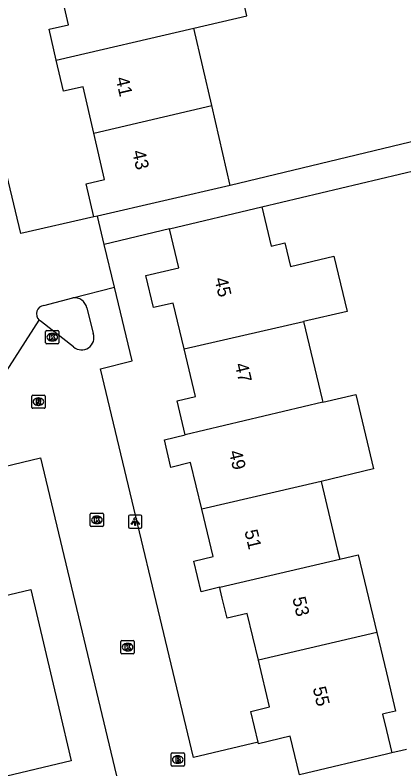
# Model space of a CAD drawing. Extents: x 158474 to 159560, y 388525 to 389605.
# Drawn here: x 159472 to 159501.3, y 388683.1 to 388739.9 of the extents above; entities that cross this region are included whole.
import ezdxf

# ---------------------------------------------------------------- set-up
doc = ezdxf.new("R2010")
doc.units = 0
for name, color, linetype in [('IMGEO_Brandkraan', 7, 'Continuous'), ('IMGEO_Kolk', 7, 'Continuous'), ('IMGEO_Lichtpunt', 7, 'Continuous'), ('IMGEO_Pand', 7, 'Continuous'), ('IMGEO_Pand_nummerreeks', 7, 'Continuous'), ('IMGEO_Rijbaan_lokaal_open', 7, 'Continuous'), ('IMGEO_Rioolput', 7, 'Continuous'), ('IMGEO_Voetpad_open', 7, 'Continuous')]:
    doc.layers.add(name, color=color, linetype=linetype)

msp = doc.modelspace()

# ---------------------------------------------------------------- linework, layer by layer
at = {"layer": 'IMGEO_Brandkraan'}
for p, q in [((159483.777, 388683.342), (159483.777, 388684.194)), ((159483.852, 388684.268), (159484.704, 388684.268)), ((159484.265, 388684.048), (159484.29, 388684.048)), ((159484.778, 388684.194), (159484.778, 388683.342)), ((159484.288, 388683.488), (159484.263, 388683.488)), ((159484.704, 388683.268), (159483.852, 388683.268))]:
    msp.add_line(p, q, dxfattribs=at)
for points in [[(159483.777, 388683.342), (159483.777, 388684.194)], [(159483.852, 388684.268), (159484.704, 388684.268)], [(159484.778, 388684.194), (159484.778, 388683.342)], [(159484.125, 388683.968), (159484.125, 388683.568), (159484.338, 388683.568)], [(159484.356, 388683.968), (159484.125, 388683.968)], [(159484.304, 388683.887), (159484.25, 388683.887), (159484.25, 388683.811)], [(159484.25, 388683.811), (159484.303, 388683.811)], [(159484.312, 388683.735), (159484.25, 388683.735), (159484.25, 388683.654)], [(159484.25, 388683.654), (159484.312, 388683.654)], [(159484.704, 388683.268), (159483.852, 388683.268)]]:
    msp.add_lwpolyline(points, dxfattribs=at)
for centre, radius, start, end in [((159483.854, 388684.192), 0.0765, 91.552, 178.448), ((159483.854, 388684.192), 0.0765, 91.552, 178.448), ((159484.702, 388684.192), 0.0765, 1.552, 88.448), ((159484.702, 388684.192), 0.0765, 1.552, 88.448), ((159484.305, 388683.849), 0.0379, 267.8285, 90.9355), ((159484.313, 388683.694), 0.0404, 269.8759, 90.5077), ((159484.344, 388683.819), 0.251, 268.6676, 293.5347), ((159484.36, 388683.823), 0.145, 59.4692, 91.5367), ((159484.385, 388683.87), 0.0922, 285.5137, 58.1501), ((159484.39, 388683.678), 0.105, 301.3115, 78.989), ((159483.854, 388683.344), 0.0765, 181.552, 268.448), ((159483.854, 388683.344), 0.0765, 181.552, 268.448), ((159484.702, 388683.344), 0.0765, 271.552, 358.448), ((159484.702, 388683.344), 0.0765, 271.552, 358.448)]:
    msp.add_arc(centre, radius, start, end, dxfattribs=at)
for centre, major_axis, ratio, start_param, end_param in [((159484.264, 388683.768), (-0.387, 0.002), 0.722429, 4.712389, 7.853982), ((159484.289, 388683.768), (-0.39, 0.002), 0.717154, 1.570796, 4.712389)]:
    msp.add_ellipse(centre, major_axis=major_axis, ratio=ratio, start_param=start_param, end_param=end_param, dxfattribs=at)
at = {"layer": 'IMGEO_Kolk'}
for p, q in [((159474.326, 388715.187), (159474.326, 388716.039)), ((159474.401, 388716.113), (159475.253, 388716.113)), ((159474.814, 388715.893), (159474.839, 388715.893)), ((159475.327, 388716.039), (159475.327, 388715.187)), ((159474.837, 388715.333), (159474.812, 388715.333)), ((159475.253, 388715.113), (159474.401, 388715.113)), ((159477.69, 388701.413), (159477.69, 388702.265)), ((159477.765, 388702.339), (159478.617, 388702.339)), ((159478.691, 388702.265), (159478.691, 388701.413)), ((159478.178, 388702.119), (159478.203, 388702.119)), ((159478.617, 388701.339), (159477.765, 388701.339)), ((159478.201, 388701.559), (159478.176, 388701.559)), ((159480, 388691.82), (159480, 388692.672)), ((159480.075, 388692.746), (159480.927, 388692.746)), ((159481.001, 388692.672), (159481.001, 388691.82)), ((159480.488, 388692.526), (159480.513, 388692.526)), ((159480.927, 388691.746), (159480.075, 388691.746)), ((159480.511, 388691.966), (159480.486, 388691.966))]:
    msp.add_line(p, q, dxfattribs=at)
for points in [[(159474.326, 388715.187), (159474.326, 388716.039)], [(159474.401, 388716.113), (159475.253, 388716.113)], [(159475.327, 388716.039), (159475.327, 388715.187)], [(159474.647, 388715.813), (159474.77, 388715.813), (159474.77, 388715.662), (159474.9, 388715.813), (159475.064, 388715.813), (159474.918, 388715.662), (159475.071, 388715.413), (159474.919, 388715.413), (159474.834, 388715.577), (159474.77, 388715.51), (159474.77, 388715.413), (159474.647, 388715.413), (159474.647, 388715.813)], [(159475.253, 388715.113), (159474.401, 388715.113)], [(159477.69, 388701.413), (159477.69, 388702.265)], [(159477.765, 388702.339), (159478.617, 388702.339)], [(159478.691, 388702.265), (159478.691, 388701.413)], [(159478.011, 388702.039), (159478.134, 388702.039), (159478.134, 388701.888), (159478.264, 388702.039), (159478.428, 388702.039), (159478.282, 388701.888), (159478.435, 388701.639), (159478.283, 388701.639), (159478.198, 388701.803), (159478.134, 388701.736), (159478.134, 388701.639), (159478.011, 388701.639), (159478.011, 388702.039)], [(159478.617, 388701.339), (159477.765, 388701.339)], [(159480, 388691.82), (159480, 388692.672)], [(159480.075, 388692.746), (159480.927, 388692.746)], [(159481.001, 388692.672), (159481.001, 388691.82)], [(159480.321, 388692.446), (159480.444, 388692.446), (159480.444, 388692.295), (159480.574, 388692.446), (159480.738, 388692.446), (159480.592, 388692.295), (159480.745, 388692.046), (159480.593, 388692.046), (159480.508, 388692.21), (159480.444, 388692.143), (159480.444, 388692.046), (159480.321, 388692.046), (159480.321, 388692.446)], [(159480.927, 388691.746), (159480.075, 388691.746)]]:
    msp.add_lwpolyline(points, dxfattribs=at)
for centre, start, end in [((159474.403, 388716.037), 91.552, 178.448), ((159474.403, 388716.037), 91.552, 178.448), ((159475.251, 388716.037), 1.552, 88.448), ((159475.251, 388716.037), 1.552, 88.448), ((159474.403, 388715.189), 181.552, 268.448), ((159474.403, 388715.189), 181.552, 268.448), ((159475.251, 388715.189), 271.552, 358.448), ((159475.251, 388715.189), 271.552, 358.448), ((159477.767, 388702.263), 91.552, 178.448), ((159477.767, 388702.263), 91.552, 178.448), ((159478.615, 388702.263), 1.552, 88.448), ((159478.615, 388702.263), 1.552, 88.448), ((159477.767, 388701.415), 181.552, 268.448), ((159477.767, 388701.415), 181.552, 268.448), ((159478.615, 388701.415), 271.552, 358.448), ((159478.615, 388701.415), 271.552, 358.448), ((159480.077, 388692.67), 91.552, 178.448), ((159480.077, 388692.67), 91.552, 178.448), ((159480.925, 388692.67), 1.552, 88.448), ((159480.925, 388692.67), 1.552, 88.448), ((159480.077, 388691.822), 181.552, 268.448), ((159480.077, 388691.822), 181.552, 268.448), ((159480.925, 388691.822), 271.552, 358.448), ((159480.925, 388691.822), 271.552, 358.448)]:
    msp.add_arc(centre, 0.0765, start, end, dxfattribs=at)
for centre, major_axis, ratio, start_param, end_param in [((159474.813, 388715.613), (-0.387, 0.002), 0.722429, 4.712389, 7.853982), ((159474.838, 388715.613), (-0.39, 0.002), 0.717154, 1.570796, 4.712389), ((159478.177, 388701.839), (-0.387, 0.002), 0.722429, 4.712389, 7.853982), ((159478.202, 388701.839), (-0.39, 0.002), 0.717154, 1.570796, 4.712389), ((159480.487, 388692.246), (-0.387, 0.002), 0.722429, 4.712389, 7.853982), ((159480.512, 388692.246), (-0.39, 0.002), 0.717154, 1.570796, 4.712389)]:
    msp.add_ellipse(centre, major_axis=major_axis, ratio=ratio, start_param=start_param, end_param=end_param, dxfattribs=at)
at = {"layer": 'IMGEO_Lichtpunt'}
for p, q in [((159480.573, 388702.112), (159480.573, 388701.305)), ((159480.573, 388702.112), (159480.573, 388701.305)), ((159481.475, 388702.207), (159480.667, 388702.207)), ((159481.475, 388702.207), (159480.667, 388702.207)), ((159481.569, 388701.305), (159481.569, 388702.112)), ((159481.569, 388701.305), (159481.569, 388702.112)), ((159480.667, 388701.211), (159481.475, 388701.211)), ((159480.667, 388701.211), (159481.475, 388701.211))]:
    msp.add_line(p, q, dxfattribs=at)
for points in [[(159480.947, 388701.776), (159480.986, 388701.748), (159480.798, 388701.486), (159480.76, 388701.513), (159480.947, 388701.776)], [(159481.049, 388701.728), (159481.096, 388701.728), (159481.096, 388701.406), (159481.049, 388701.406), (159481.049, 388701.728)], [(159481.159, 388701.748), (159481.197, 388701.775), (159481.384, 388701.513), (159481.345, 388701.485), (159481.159, 388701.748)]]:
    msp.add_lwpolyline(points, dxfattribs=at)
msp.add_circle((159481.072, 388701.91), 0.0994, dxfattribs=at)
for centre, start, end in [((159480.667, 388702.112), 90, 180), ((159480.667, 388702.112), 90, 180), ((159481.475, 388702.112), 0, 90), ((159481.475, 388702.112), 0, 90), ((159480.667, 388701.305), 180, 270), ((159480.667, 388701.305), 180, 270), ((159481.475, 388701.305), 270, 0), ((159481.475, 388701.305), 270, 360)]:
    msp.add_arc(centre, 0.0946, start, end, dxfattribs=at)
at = {"layer": 'IMGEO_Pand'}
for points in [[(159485.492, 388738.917), (159489.487, 388739.841), (159487.48, 388748.522), (159484.944, 388747.935), (159484.904, 388748.11)], [(159475.126, 388736.498), (159474.587, 388738.829), (159476.044, 388739.166), (159475.207, 388742.785), (159477.655, 388743.351), (159477.149, 388745.539), (159477.032, 388746.044), (159476.99, 388746.224)], [(159475.126, 388736.498), (159485.492, 388738.917)], [(159486.844, 388733.071), (159485.492, 388738.917)], [(159477.948, 388731.007), (159477.14, 388734.502), (159475.666, 388734.161), (159475.126, 388736.498)], [(159477.948, 388731.007), (159486.844, 388733.071)], [(159488.236, 388727.052), (159486.844, 388733.071)], [(159477.961, 388724.676), (159477.384, 388727.172), (159478.761, 388727.491), (159477.948, 388731.007)], [(159488.236, 388727.052), (159478.232, 388724.739)], [(159483.655, 388723.79), (159490.608, 388725.444)], [(159490.608, 388725.444), (159491.312, 388722.488), (159492.355, 388722.736), (159492.781, 388720.946), (159496.042, 388721.721), (159497.032, 388717.56), (159493.765, 388716.807)], [(159478.232, 388724.739), (159477.961, 388724.676)], [(159484.749, 388714.729), (159483.925, 388718.19), (159482.456, 388717.84), (159481.879, 388720.265), (159484.354, 388720.854), (159483.655, 388723.79)], [(159484.749, 388714.729), (159493.765, 388716.807)], [(159493.765, 388716.807), (159495.166, 388710.921), (159495.214, 388710.718)], [(159484.838, 388708.251), (159484.228, 388710.811), (159485.603, 388711.138), (159484.749, 388714.729)], [(159495.214, 388710.718), (159497.685, 388711.303), (159499.022, 388705.682), (159495.082, 388704.745)], [(159495.214, 388710.718), (159484.838, 388708.251)], [(159486.085, 388702.652), (159485.251, 388706.155), (159483.762, 388705.801), (159483.269, 388707.873), (159484.838, 388708.251)], [(159495.082, 388704.745), (159486.085, 388702.652)], [(159495.082, 388704.745), (159496.298, 388699.635), (159496.435, 388699.058), (159496.478, 388698.875)], [(159487.442, 388696.755), (159486.033, 388696.425), (159485.482, 388698.737), (159486.934, 388699.083), (159486.085, 388702.652)], [(159487.442, 388696.755), (159496.478, 388698.875)], [(159496.478, 388698.875), (159497.883, 388699.205), (159499.275, 388693.353)], [(159466.908, 388696.655), (159469.246, 388697.207), (159469.596, 388695.73), (159473.2, 388696.582), (159475.31, 388687.65), (159476.251, 388683.669), (159470.309, 388682.265), (159469.368, 388686.246)], [(159490.352, 388691.252), (159489.511, 388694.789), (159487.995, 388694.429), (159487.635, 388695.941), (159487.482, 388696.586), (159487.442, 388696.755)], [(159499.275, 388693.353), (159490.352, 388691.252)], [(159499.275, 388693.353), (159500, 388690.305), (159500.686, 388687.421), (159500, 388687.258), (159499.706, 388687.188), (159500, 388685.953), (159500.4, 388684.271)], [(159490.331, 388685.088), (159489.78, 388687.404), (159491.188, 388687.739), (159490.352, 388691.252)], [(159500.4, 388684.271), (159500, 388684.176), (159493.451, 388682.617), (159492.759, 388685.528), (159490.362, 388684.958), (159490.331, 388685.088)]]:
    msp.add_lwpolyline(points, dxfattribs=at)
at = {"layer": 'IMGEO_Rijbaan_lokaal_open'}
for points in [[(159476.364, 388718.576), (159479.519, 388719.374)], [(159490.331, 388685.088), (159485.469, 388683.929), (159478.455, 388713.218), (159480.849, 388713.829), (159479.519, 388719.374)], [(159477.421, 388717.817), (159477.905, 388715.891)], [(159469.521, 388710.179), (159473.838, 388716.897)], [(159476.434, 388714.882), (159474.011, 388716.782), (159473.838, 388716.897)], [(159469.124, 388705.368), (159473.944, 388706.509), (159481.42, 388675.178)], [(159501.503, 388684.533), (159501.198, 388684.461), (159500.4, 388684.271)]]:
    msp.add_lwpolyline(points, dxfattribs=at)
for centre, radius, start, end in [((159476.495, 388717.643), 0.942, 10.6419, 97.9961), ((159477.043, 388715.571), 0.92, 228.5518, 20.3428)]:
    msp.add_arc(centre, radius, start, end, dxfattribs=at)
at = {"layer": 'IMGEO_Rioolput'}
for p, q in [((159473.279, 388710.325), (159473.279, 388711.177)), ((159473.354, 388711.251), (159474.206, 388711.251)), ((159473.767, 388711.031), (159473.792, 388711.031)), ((159474.28, 388711.177), (159474.28, 388710.325)), ((159474.206, 388710.251), (159473.354, 388710.251)), ((159473.79, 388710.471), (159473.765, 388710.471))]:
    msp.add_line(p, q, dxfattribs=at)
for points in [[(159473.279, 388710.325), (159473.279, 388711.177)], [(159473.354, 388711.251), (159474.206, 388711.251)], [(159473.868, 388710.949), (159473.616, 388710.951), (159473.616, 388710.551)], [(159473.794, 388710.87), (159473.74, 388710.87), (159473.74, 388710.789)], [(159473.74, 388710.789), (159473.792, 388710.789)], [(159474.28, 388711.177), (159474.28, 388710.325)], [(159474.206, 388710.251), (159473.354, 388710.251)], [(159473.616, 388710.551), (159473.74, 388710.551), (159473.74, 388710.713), (159473.751, 388710.713)], [(159473.798, 388710.684), (159473.869, 388710.551), (159474.009, 388710.551), (159473.944, 388710.677)]]:
    msp.add_lwpolyline(points, dxfattribs=at)
for centre, radius, start, end in [((159473.356, 388711.175), 0.0765, 91.552, 178.448), ((159473.356, 388711.175), 0.0765, 91.552, 178.448), ((159473.776, 388710.978), 0.19, 274.7715, 282.9687), ((159473.8, 388710.774), 0.0964, 77.0061, 93.1865), ((159473.814, 388710.831), 0.0378, 276.6634, 79.6772), ((159473.867, 388710.839), 0.109, 350.3612, 89.416), ((159473.865, 388710.839), 0.112, 277.5842, 350.9817), ((159474.204, 388711.175), 0.0765, 1.552, 88.448), ((159474.204, 388711.175), 0.0765, 1.552, 88.448), ((159473.356, 388710.327), 0.0765, 181.552, 268.448), ((159473.356, 388710.327), 0.0765, 181.552, 268.448), ((159473.75, 388710.66), 0.0533, 26.0293, 88.6989), ((159473.849, 388710.624), 0.108, 29.5134, 73.7905), ((159474.204, 388710.327), 0.0765, 271.552, 358.448), ((159474.204, 388710.327), 0.0765, 271.552, 358.448)]:
    msp.add_arc(centre, radius, start, end, dxfattribs=at)
for centre, major_axis, ratio, start_param, end_param in [((159473.766, 388710.751), (-0.387, 0.002), 0.722429, 4.712389, 7.853982), ((159473.791, 388710.751), (-0.39, 0.002), 0.717154, 1.570796, 4.712389)]:
    msp.add_ellipse(centre, major_axis=major_axis, ratio=ratio, start_param=start_param, end_param=end_param, dxfattribs=at)
at = {"layer": 'IMGEO_Voetpad_open'}
for points in [[(159477.961, 388724.676), (159472.456, 388723.428), (159467.533, 388743.992), (159474.607, 388745.654), (159473.743, 388749.134)], [(159507.218, 388731.633), (159488.236, 388727.052)], [(159490.608, 388725.444), (159508.398, 388729.676), (159510.586, 388720.729)], [(159478.743, 388722.607), (159478.232, 388724.739)], [(159483.655, 388723.79), (159478.743, 388722.607)], [(159479.519, 388719.374), (159478.743, 388722.607)], [(159474.198, 388718.012), (159476.364, 388718.576)]]:
    msp.add_lwpolyline(points, dxfattribs=at)
msp.add_arc((159474.277, 388717.371), 0.646, 97.0034, 227.2092, dxfattribs=at)

# ---------------------------------------------------------------- texts
at = {"layer": 'IMGEO_Pand_nummerreeks'}
for s, rotation, p in [('41', 283.0821, (159479.588, 388735.132)), ('43', 283.0821, (159480.832, 388729.609)), ('45', 283.3841, (159487.034, 388720.009)), ('47', 283.3831, (159488.566, 388713.557)), ('49', 283.3831, (159488.119, 388706.977)), ('51', 283.3841, (159489.295, 388700.99)), ('53', 283.3841, (159492.909, 388695.926)), ('55', 283.3831, (159494.441, 388689.155))]:
    msp.add_text(s, height=1, rotation=rotation, dxfattribs=at).set_placement(p)

doc.saveas('drawing.dxf')
